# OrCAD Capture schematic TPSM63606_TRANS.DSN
size D; title: TPSM63606 High-Density, 3-V to 36-V Input, 1-V to 16-V Output,; rev: 1.0; note: Datasheet: SLVSGB4     EVM: SLVUC93; note: Synchronous Step Down Converter
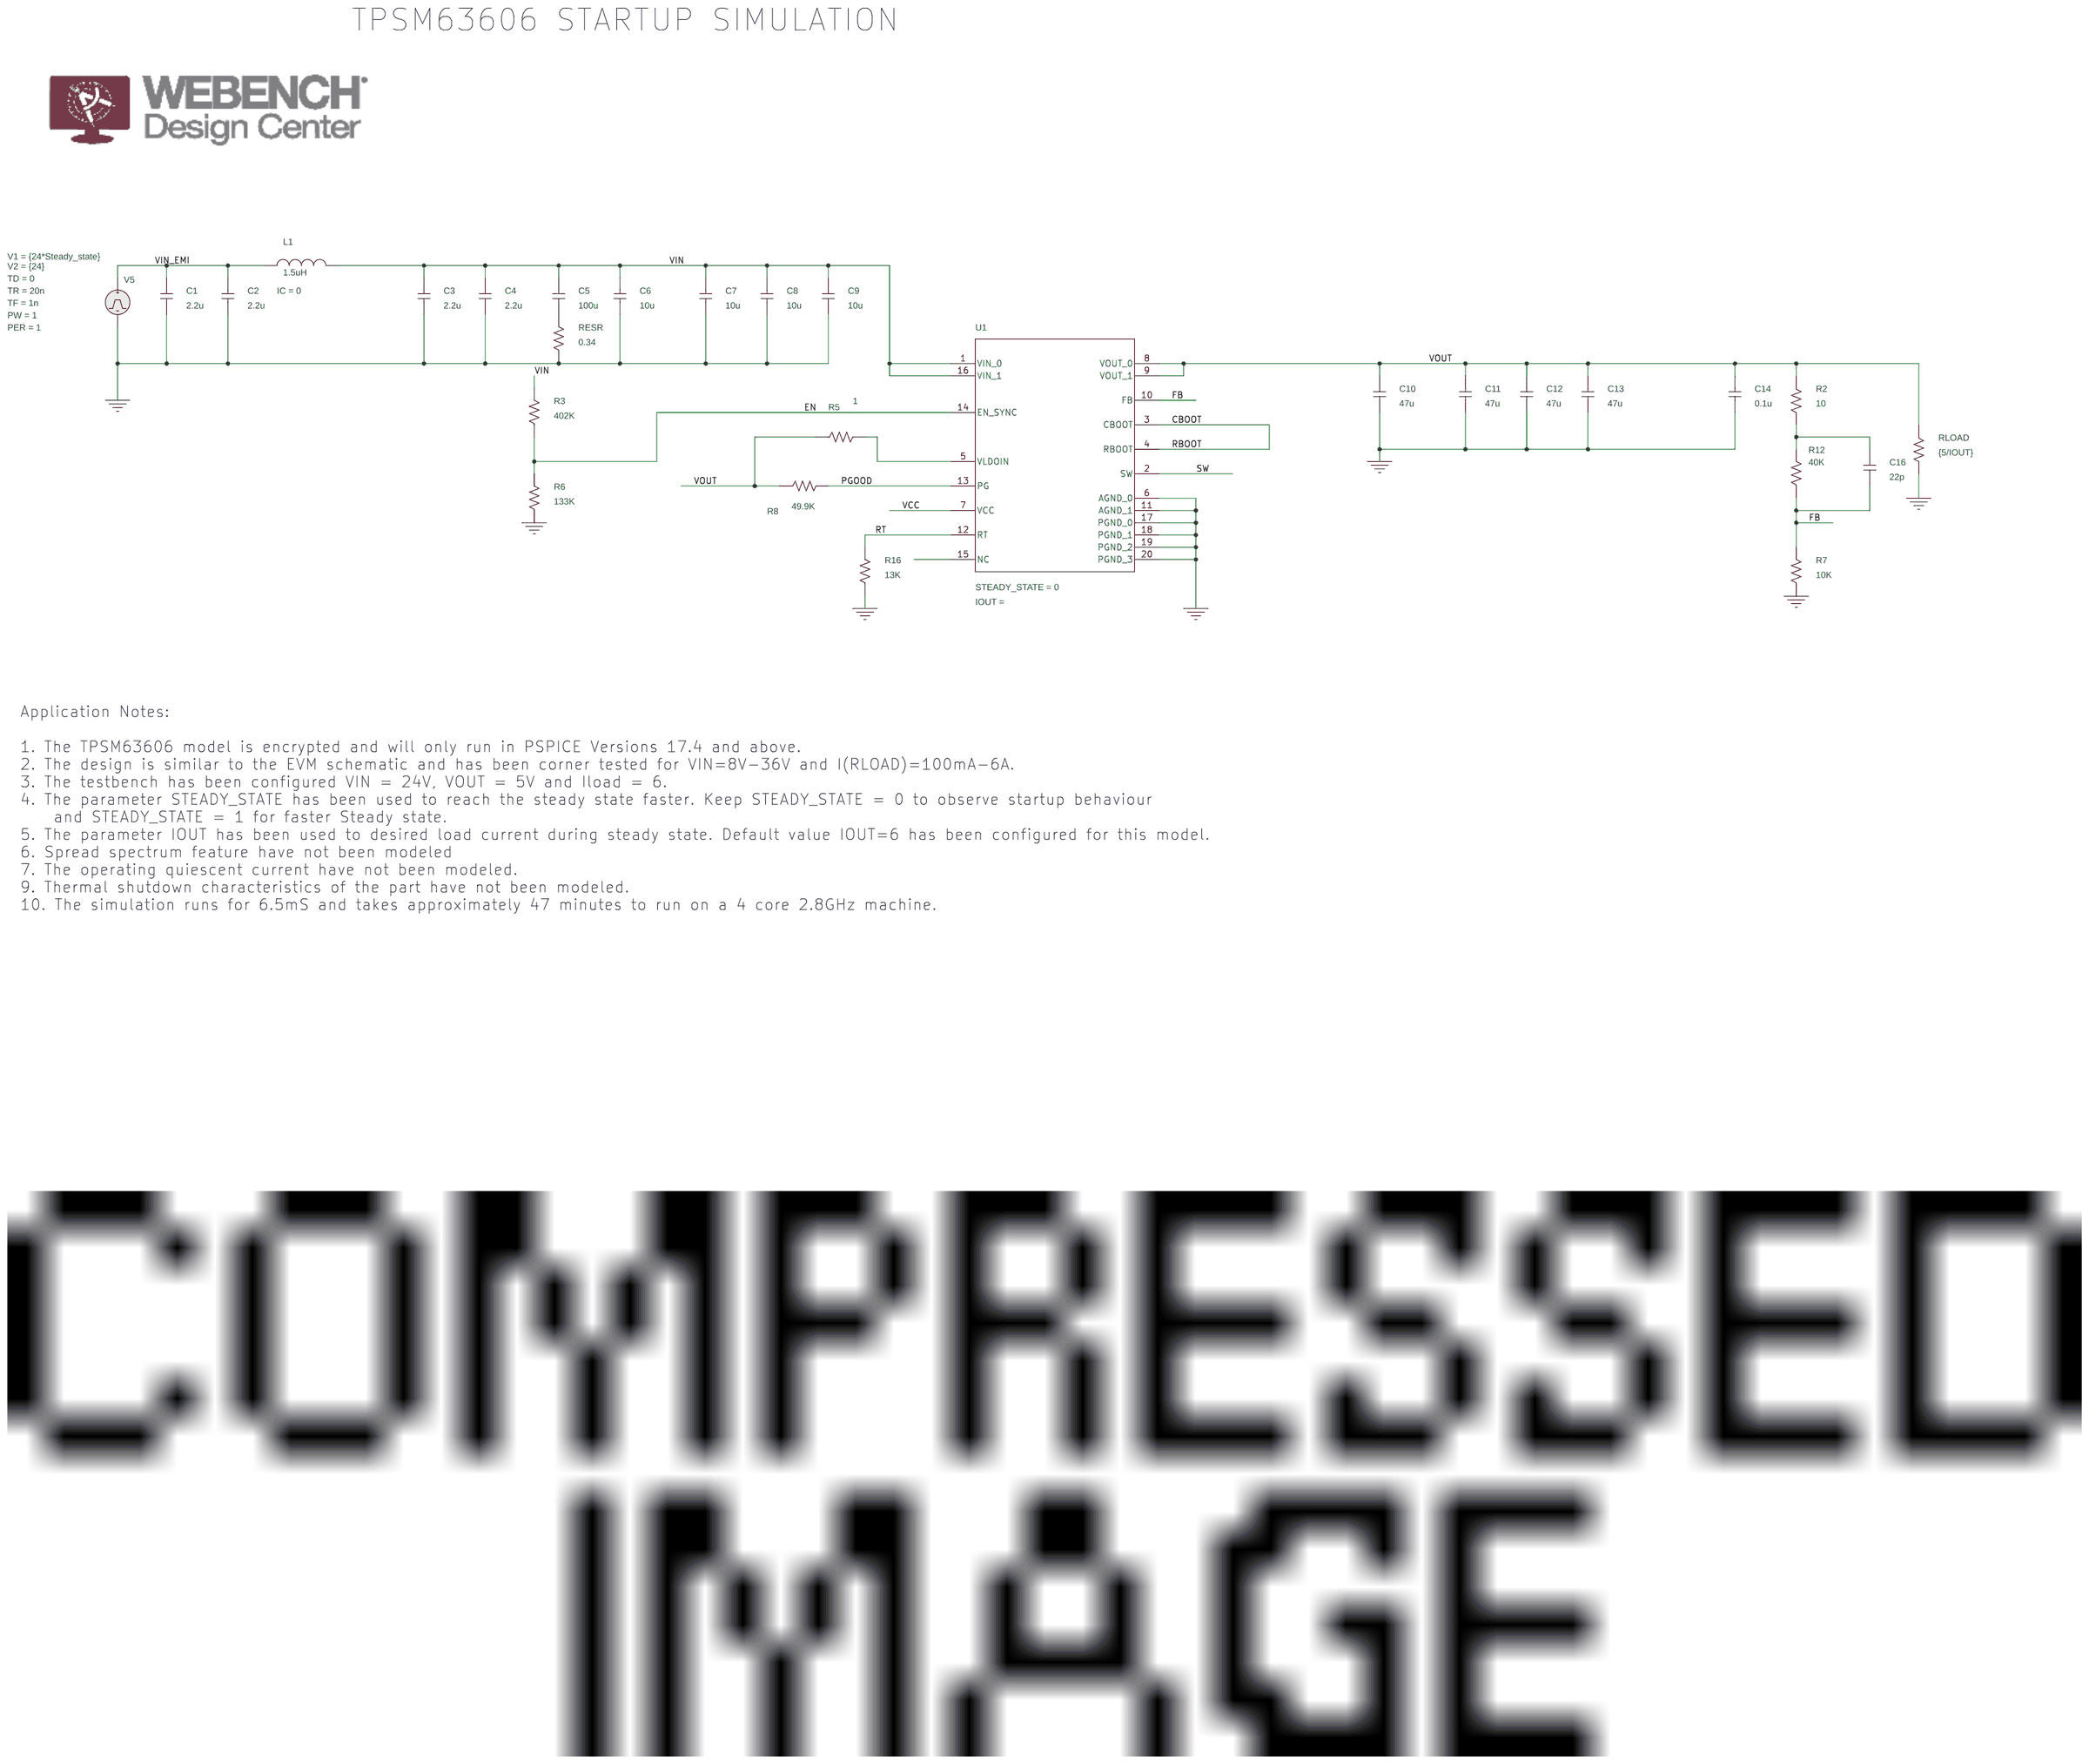
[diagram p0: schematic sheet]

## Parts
C1  2.2u  [RAD/CK05]
C2  2.2u  [RAD/CK05]
C3  2.2u  [RAD/CK05]
C4  2.2u  [RAD/CK05]
C5  100u  [RAD/CK05]
C6  10u  [RAD/CK05]
C7  10u  [RAD/CK05]
C8  10u  [RAD/CK05]
C9  10u  [RAD/CK05]
C10  47u  [RAD/CK05]
C11  47u  [RAD/CK05]
C12  47u  [RAD/CK05]
C13  47u  [RAD/CK05]
C14  0.1u  [RAD/CK05]
C16  22p  [RAD/CK05]
L1  1.5uH  [DISC/.350x.175/LS.200x.100/.034]
R2  10  [AX/RC05]
R3  402K  [AX/RC05]
R5  1  [AX/RC05]
R6  133K  [AX/RC05]
R7  10K  [AX/RC05]
R8  49.9K  [AX/RC05]
R12  40K  [AX/RC05]
R16  13K  [AX/RC05]
RESR  0.34  [AX/RC05]
RLOAD  {5/IOUT}  [AX/RC05]
U1  Value  [RDL0020A-MFG]
V5  VPULSE

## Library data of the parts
C1-C14 C16 = C: IC: 0
L1 = L: IC: 0
R2 R3 R6 R7 R12 R16 RESR RLOAD = R
R5 R8 = r
U1 = TPSM63606RDL_TRANS: STEADY_STATE: 0
V5 = VPULSE: PER: 1; PW: 1; TD: 0; TF: 1n; TR: 20n; V1: {24*Steady_state}; V2: {24}

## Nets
VCC: U1.7(VCC)
VIN: C3.1 C4.1 C5.1 C6.1 C7.1 C8.1 C9.1 L1.2 R3.2 U1.1(VIN_0) U1.16(VIN_1)
VIN_EMI: C1.1 C2.1 L1.1 V5.1(+)
0: C1.2 C2.2 C3.2 C4.2 C6.2 C7.2 C8.2 C9.2 C10.2 C11.2 C12.2 C13.2 C14.2 R6.1 R7.1 R16.1 RESR.1 RLOAD.2 U1.6(AGND_0) U1.11(AGND_1) U1.17(PGND_0) U1.18(PGND_1) U1.19(PGND_2) U1.20(PGND_3) V5.2(-)
CBOOT: U1.3(CBOOT) U1.4(RBOOT)
EN: R3.1 R6.2 U1.14(EN_SYNC)
FB: C16.2 R7.2 R12.1 U1.10(FB)
PGOOD: R8.2 U1.13(PG)
RT: R16.2 U1.12(RT)
SW: U1.2(SW)
VOUT: C10.1 C11.1 C12.1 C13.1 C14.1 R2.1 R5.1 R8.1 RLOAD.1 U1.8(VOUT_0) U1.9(VOUT_1)
N48197: C16.1 R2.2 R12.2
N48215: R5.2 U1.5(VLDOIN)
N16773594: C5.2 RESR.2

Not connected (* = marked no-connect by the designer): U1 15(NC)

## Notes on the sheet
- TPSM63606 STARTUP SIMULATION
- Application Notes:
  1. The TPSM63606 model is encrypted and will only run in PSPICE Versions 17.4 and above.
  2. The design is similar to the EVM schematic and has been corner tested for VIN=8V-36V and I(RLOAD)=100mA-6A.
  3. The testbench has been configured VIN = 24V, VOUT = 5V and Iload = 6.
  4. The parameter STEADY_STATE has been used to reach the steady state faster. Keep STEADY_STATE = 0 to observe startup behaviour
      and STEADY_STATE = 1 for faster Steady state.
  5. The parameter IOUT has been used to desired load current during steady state. Default value IOUT=6 has been configured for this model.
  6. Spread spectrum feature have not been modeled
  7. The operating quiescent current have not been modeled.
  9. Thermal shutdown characteristics of the part have not been modeled.
  10. The simulation runs for 6.5mS and takes approximately 47 minutes to run on a 4 core 2.8GHz machine.
